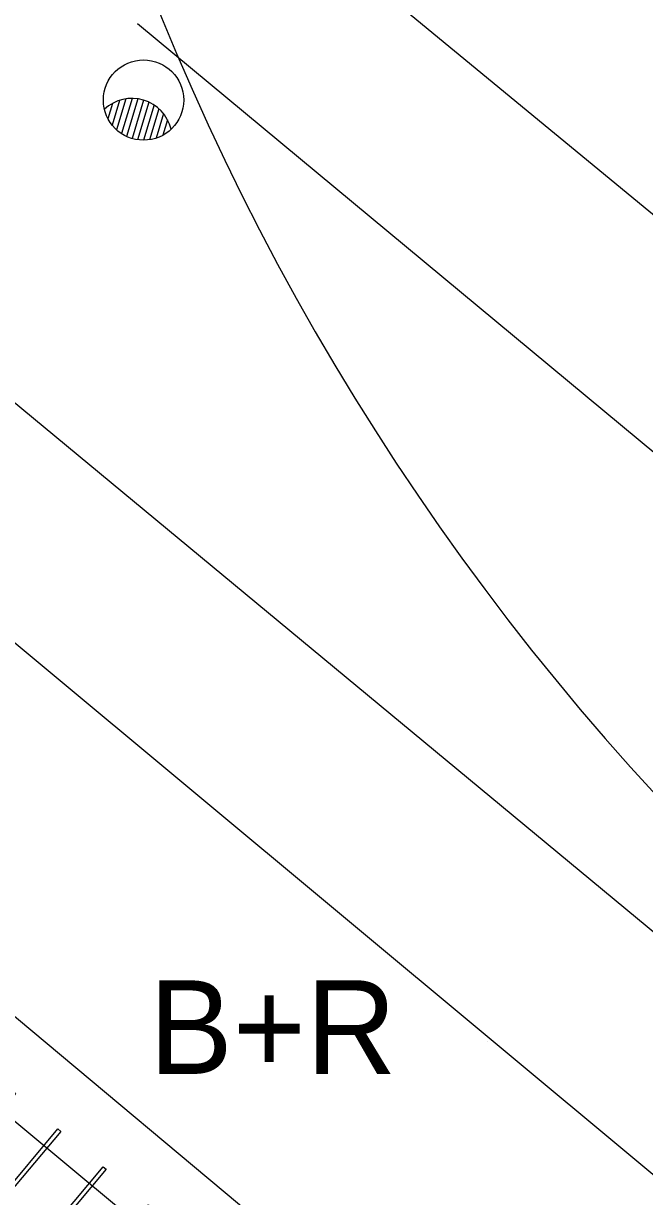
# Model space of a CAD drawing. Extents: x -438200 to -437954, y -1133133 to -1132850.
# Drawn here: x -438085 to -438078.37, y -1132974.91 to -1132962.38 of the extents above; entities that cross this region are included whole.
import ezdxf

# ---------------------------------------------------------------- set-up
doc = ezdxf.new("R2010")
doc.units = 0
for name, color, linetype in [('Default', 7, 'Continuous'), ('EL3', 7, 'Continuous'), ('MOBILIÁŘ', 7, 'Continuous'), ('Vrstva 1', 7, 'Continuous'), ('Vrstva 10', 7, 'Continuous'), ('Vrstva 53', 7, 'Continuous')]:
    doc.layers.add(name, color=color, linetype=linetype)

# ---------------------------------------------------------------- blocks, each defined once
blk = doc.blocks.new('A$C73EC33FB')
at = {"layer": 'Default'}
for points in [[(-39000, 25012), (0, 25012), (0, 0), (-39000, 0)], [(-32310, 18759), (-31900, 18759), (-31900, 9105), (-32310, 9105)], [(-26014, 18759), (-25605, 18759), (-25605, 9105), (-26014, 9105)], [(-19705, 18759), (-19295, 18759), (-19295, 9105), (-19705, 9105)], [(-13409, 18759), (-13000, 18759), (-13000, 9105), (-13409, 9105)], [(-7100, 18759), (-6690, 18759), (-6690, 9105), (-7100, 9105)]]:
    blk.add_lwpolyline(points, close=True, dxfattribs=at)
blk = doc.blocks.new('ELJL31_2_1_1')
at = {"layer": 'EL3'}
for p, q in [((10.50516, 25), (24.4949, 25)), ((3.37727, 15), (31.62278, 15)), ((6.27724, 20), (28.72281, 20)), ((0, 0), (35, 0)), ((0.35902, 5), (34.64102, 5)), ((1.45902, 10), (33.54102, 10)), ((0.35902, -5), (34.64102, -5)), ((1.45902, -10), (33.54102, -10)), ((3.37727, -15), (31.62278, -15)), ((6.27724, -20), (28.72281, -20)), ((10.50516, -25), (24.4949, -25))]:
    blk.add_line(p, q, dxfattribs=at)
blk.add_circle((0, 0), 35, dxfattribs=at)
blk.add_arc((35, 0), 34.99996, 119.999947, 239.999954, dxfattribs=at)

msp = doc.modelspace()

# ---------------------------------------------------------------- linework, layer by layer
at = {"layer": 'Vrstva 1'}
for p, q in [((-438083.784, -1132962.385), (-438083.784, -1132962.385)), ((-438078.503, -1132971.89), (-438078.503, -1132971.89)), ((-438080.042, -1132973.257), (-438080.042, -1132973.257))]:
    msp.add_line(p, q, dxfattribs=at)
msp.add_arc((-438057.962, -1132951.913), 27.6, 199.5386, 254.3601, dxfattribs=at)
msp.add_arc((-438057.962, -1132951.913), 27.6, 199.5386, 254.3601, dxfattribs=at)
at = {"layer": 'Vrstva 10'}
for points in [[(-438082.411, -1132961.014), (-438066.062, -1132974.491)], [(-438083.784, -1132962.385), (-438067.332, -1132976.054)], [(-438086.926, -1132964.916), (-438070.59, -1132978.455)], [(-438088.082, -1132966.508), (-438071.892, -1132980)], [(-438091.201, -1132969.023), (-438075.155, -1132982.388)]]:
    msp.add_lwpolyline(points, dxfattribs=at)

# ---------------------------------------------------------------- block references
at = {"layer": 'MOBILIÁŘ', "xscale": 0.0001, "yscale": 9.999999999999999e-05, "rotation": -39.966187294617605}
msp.add_blockref('A$C73EC33FB', (-438083.843, -1132977.3), dxfattribs=at)
msp.add_blockref('A$C73EC33FB', (-438083.843, -1132977.3), dxfattribs=at)
at = {"layer": 'Vrstva 53', "xscale": 0.01225, "yscale": 0.012249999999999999, "rotation": -106.66592339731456}
msp.add_blockref('ELJL31_2_1_1', (-438083.718, -1132963.203), dxfattribs=at)

# ---------------------------------------------------------------- texts
at = {"layer": 'Vrstva 1'}
msp.add_text('B+R', height=1, dxfattribs=at).set_placement((-438083.658, -1132973.604))
msp.add_text('B+R', height=1, dxfattribs=at).set_placement((-438083.658, -1132973.604))

doc.saveas('drawing.dxf')
